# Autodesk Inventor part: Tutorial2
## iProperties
Shininess: 64.0
Length Units: 11269
Angle Units: 11279
Time Units: 11290
Mass Units: 11283
Length Display Precision: 3
Angle Display Precision: 2
Compacted: True
Part Number: Tutorial2
Document SubType Name: Modeling
Created: 2002-11
Designer: deepak
Density: 0.0
Volumn: 0.0
Area: 0.0
PropertySet Name: Model Information
Control State: 0
Master: False
Checked Out: False
Author: deepak
